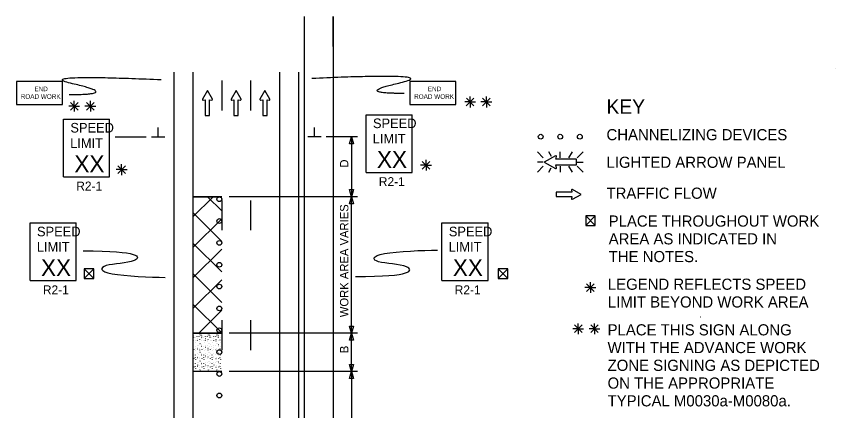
# Model space of a CAD drawing. Extents: x 16590 to 19508, y 5703 to 6974.
# Drawn here: x 16741 to 17424, y 6645 to 6974 of the extents above; entities that cross this region are included whole.
import ezdxf

# ---------------------------------------------------------------- set-up
doc = ezdxf.new("R2010")
doc.units = 0
for name, color, linetype in [('ALI_LEGAL_EX', 7, 'Continuous'), ('BORDER', 7, 'Continuous'), ('MT_SCRATCH_LEVEL_E', 7, 'Continuous'), ('PAVT_EDGE_EX', 7, 'Continuous'), ('TRAFFIC_SIGNS_PR', 7, 'Continuous'), ('TYPICAL_TEXT_DIMEN_EX', 7, 'Continuous'), ('TYPICAL_TEXT_DIMEN_PR', 7, 'Continuous')]:
    doc.layers.add(name, color=color, linetype=linetype)

msp = doc.modelspace()

# ---------------------------------------------------------------- linework, layer by layer
at = {"layer": 'ALI_LEGAL_EX'}
for p, q in [((16980.68, 6974.12), (16980.68, 6155.98)), ((17004.68, 6974.12), (17004.68, 6155.98)), ((16980.68, 6922.21), (16980.68, 6058.3)), ((17004.68, 6922.21), (17004.68, 6058.3))]:
    msp.add_line(p, q, dxfattribs=at)
for points in [[(17004.68, 6949.12), (17004.68, 6974.12)], [(16911.96, 6920.69), (16911.96, 6895.69)], [(16935.96, 6920.69), (16935.96, 6895.69)], [(16911.96, 6820.69), (16911.96, 6795.69)], [(16935.96, 6820.69), (16935.96, 6795.69)], [(16911.96, 6720.69), (16911.96, 6695.69)], [(16935.96, 6720.69), (16935.96, 6695.69)]]:
    msp.add_lwpolyline(points, dxfattribs=at)
at = {"layer": 'BORDER'}
msp.add_line((17423.55, 6930.8), (17423.55, 6930.8), dxfattribs=at)
at = {"layer": 'MT_SCRATCH_LEVEL_E'}
for p, q in [((16899.96, 6912.2), (16895.85, 6904.96)), ((16904.1, 6904.96), (16899.96, 6912.2)), ((16923.86, 6912.2), (16919.75, 6904.96)), ((16928.01, 6904.96), (16923.86, 6912.2)), ((16947.91, 6912.2), (16943.8, 6904.96)), ((16952.06, 6904.96), (16947.91, 6912.2)), ((16896.33, 6904.28), (16898.1, 6904.59)), ((16898.1, 6904.59), (16898.1, 6891.34)), ((16901.85, 6891.34), (16901.85, 6904.59)), ((16901.85, 6904.59), (16903.62, 6904.28)), ((16920.23, 6904.28), (16922.01, 6904.59)), ((16922.01, 6904.59), (16922.01, 6891.34)), ((16925.75, 6891.34), (16925.75, 6904.59)), ((16925.75, 6904.59), (16927.53, 6904.28)), ((16944.28, 6904.28), (16946.06, 6904.59)), ((16946.06, 6904.59), (16946.06, 6891.34)), ((16949.8, 6891.34), (16949.8, 6904.59)), ((16949.8, 6904.59), (16951.58, 6904.28)), ((16898.1, 6891.34), (16901.85, 6891.34)), ((16922.01, 6891.34), (16925.75, 6891.34)), ((16946.06, 6891.34), (16949.8, 6891.34)), ((17203.46, 6829.33), (17203.77, 6827.55)), ((17211.38, 6825.7), (17204.14, 6829.81)), ((17203.77, 6827.55), (17190.52, 6827.55)), ((17190.52, 6827.55), (17190.52, 6823.81)), ((17190.52, 6823.81), (17203.77, 6823.81)), ((17203.77, 6823.81), (17203.46, 6822.03)), ((17204.14, 6821.55), (17211.38, 6825.7))]:
    msp.add_line(p, q, dxfattribs=at)
for centre, start, end in [((16896.25, 6904.74), 150.42484, 279.96381), ((16903.69, 6904.74), 260.03619, 29.77312), ((16920.16, 6904.74), 150.42484, 279.96381), ((16927.6, 6904.74), 260.03619, 29.77312), ((16944.21, 6904.74), 150.42484, 279.96381), ((16951.65, 6904.74), 260.03619, 29.77312), ((17203.92, 6829.4), 60.42484, 189.96381), ((17203.92, 6821.96), 170.03619, 299.77312)]:
    msp.add_arc(centre, 0.463, start, end, dxfattribs=at)
at = {"layer": 'PAVT_EDGE_EX'}
for p, q in [((16871.96, 6927.73), (16871.96, 6263.8)), ((16887.96, 6927.73), (16887.96, 6263.8)), ((16959.96, 6927.73), (16959.96, 6263.8)), ((16975.96, 6927.73), (16975.96, 6263.8)), ((16887.96, 6823.76), (16911.96, 6823.76)), ((16887.96, 6806.86), (16904.85, 6823.76)), ((16912.05, 6823.76), (16888.05, 6823.76)), ((16911.96, 6811.94), (16900.14, 6823.76)), ((16911.96, 6786.49), (16887.96, 6810.49)), ((16887.96, 6781.4), (16911.96, 6805.4)), ((16911.96, 6761.03), (16887.96, 6785.03)), ((16887.96, 6755.95), (16911.96, 6779.95)), ((16911.96, 6735.58), (16887.96, 6759.58)), ((16887.96, 6730.49), (16911.96, 6754.49)), ((16911.96, 6710.12), (16887.96, 6734.12)), ((16892.95, 6710.03), (16912.05, 6729.12)), ((16911.96, 6710.03), (16887.96, 6710.03)), ((16912.05, 6710.03), (16888.05, 6710.03)), ((16888.05, 6710.03), (16912.05, 6710.03)), ((16888.35, 6706.21), (16888.3, 6706.13)), ((16888.44, 6707.48), (16888.38, 6707.6)), ((16889.89, 6706.35), (16889.83, 6706.27)), ((16890.46, 6709.68), (16890.4, 6709.79)), ((16891.5, 6707.18), (16891.45, 6707.3)), ((16891.68, 6705.29), (16891.62, 6705.22)), ((16892.95, 6707.03), (16892.9, 6706.95)), ((16893.82, 6708.41), (16893.77, 6708.33)), ((16894.56, 6708.44), (16894.51, 6708.36)), ((16895.24, 6706.21), (16895.19, 6706.13)), ((16895.32, 6707.48), (16895.27, 6707.6)), ((16896.77, 6706.35), (16896.72, 6706.27)), ((16897.34, 6709.68), (16897.29, 6709.79)), ((16898.39, 6707.18), (16898.34, 6707.3)), ((16898.56, 6705.29), (16898.51, 6705.22)), ((16899.84, 6707.03), (16899.79, 6706.95)), ((16900.71, 6708.41), (16900.66, 6708.33)), ((16901.45, 6708.44), (16901.4, 6708.36)), ((16902.13, 6706.21), (16902.08, 6706.13)), ((16902.21, 6707.48), (16902.16, 6707.6)), ((16903.66, 6706.35), (16903.61, 6706.27)), ((16904.23, 6709.68), (16904.18, 6709.79)), ((16905.28, 6707.18), (16905.23, 6707.3)), ((16905.45, 6705.29), (16905.4, 6705.22)), ((16906.73, 6707.03), (16906.68, 6706.95)), ((16907.6, 6708.41), (16907.55, 6708.33)), ((16908.33, 6708.44), (16908.28, 6708.36)), ((16909.02, 6706.21), (16908.97, 6706.13)), ((16909.1, 6707.48), (16909.05, 6707.6)), ((16910.55, 6706.35), (16910.5, 6706.27)), ((16911.12, 6709.68), (16911.07, 6709.79)), ((16912.05, 6710.03), (16912.05, 6710.03)), ((16888.35, 6698.93), (16888.3, 6698.85)), ((16888.44, 6700.19), (16888.38, 6700.31)), ((16888.56, 6703.57), (16888.54, 6703.45)), ((16889.84, 6704.14), (16889.78, 6704.07)), ((16889.89, 6699.07), (16889.83, 6698.99)), ((16890.46, 6702.39), (16890.4, 6702.51)), ((16891.5, 6699.9), (16891.45, 6700.01)), ((16891.63, 6703.89), (16891.58, 6704.01)), ((16891.68, 6698.01), (16891.62, 6697.93)), ((16892.95, 6699.74), (16892.9, 6699.67)), ((16893.41, 6703.22), (16893.36, 6703.15)), ((16893.6, 6704.42), (16893.55, 6704.54)), ((16893.82, 6701.12), (16893.77, 6701.05)), ((16894.56, 6701.15), (16894.51, 6701.08)), ((16895.24, 6698.93), (16895.19, 6698.85)), ((16895.32, 6700.19), (16895.27, 6700.31)), ((16895.44, 6703.57), (16895.43, 6703.45)), ((16896.72, 6704.14), (16896.67, 6704.07)), ((16896.77, 6699.07), (16896.72, 6698.99)), ((16897.34, 6702.39), (16897.29, 6702.51)), ((16898.39, 6699.9), (16898.34, 6700.01)), ((16898.52, 6703.89), (16898.47, 6704.01)), ((16898.56, 6698.01), (16898.51, 6697.93)), ((16899.84, 6699.74), (16899.79, 6699.67)), ((16900.3, 6703.22), (16900.25, 6703.15)), ((16900.49, 6704.42), (16900.44, 6704.54)), ((16900.71, 6701.12), (16900.66, 6701.05)), ((16901.45, 6701.15), (16901.4, 6701.08)), ((16902.13, 6698.93), (16902.08, 6698.85)), ((16902.21, 6700.19), (16902.16, 6700.31)), ((16902.33, 6703.57), (16902.32, 6703.45)), ((16903.61, 6704.14), (16903.56, 6704.07)), ((16903.66, 6699.07), (16903.61, 6698.99)), ((16904.23, 6702.39), (16904.18, 6702.51)), ((16905.28, 6699.9), (16905.23, 6700.01)), ((16905.41, 6703.89), (16905.36, 6704.01)), ((16905.45, 6698.01), (16905.4, 6697.93)), ((16906.73, 6699.74), (16906.68, 6699.67)), ((16907.19, 6703.22), (16907.14, 6703.15)), ((16907.38, 6704.42), (16907.33, 6704.54)), ((16907.6, 6701.12), (16907.55, 6701.05)), ((16908.33, 6701.15), (16908.28, 6701.08)), ((16909.02, 6698.93), (16908.97, 6698.85)), ((16909.1, 6700.19), (16909.05, 6700.31)), ((16909.22, 6703.57), (16909.21, 6703.45)), ((16910.5, 6704.14), (16910.45, 6704.07)), ((16910.55, 6699.07), (16910.5, 6698.99)), ((16911.12, 6702.39), (16911.07, 6702.51)), ((16888.35, 6691.64), (16888.3, 6691.56)), ((16888.44, 6692.91), (16888.38, 6693.03)), ((16888.56, 6696.28), (16888.54, 6696.16)), ((16889.84, 6696.86), (16889.78, 6696.78)), ((16889.89, 6691.78), (16889.83, 6691.7)), ((16890.46, 6695.11), (16890.4, 6695.22)), ((16891.5, 6692.61), (16891.45, 6692.73)), ((16891.63, 6696.61), (16891.58, 6696.72)), ((16892.95, 6692.46), (16892.9, 6692.38)), ((16893.41, 6695.94), (16893.36, 6695.86)), ((16893.6, 6697.14), (16893.55, 6697.25)), ((16893.82, 6693.84), (16893.77, 6693.76)), ((16894.56, 6693.87), (16894.51, 6693.79)), ((16895.24, 6691.64), (16895.19, 6691.56)), ((16895.32, 6692.91), (16895.27, 6693.03)), ((16895.44, 6696.28), (16895.43, 6696.16)), ((16896.72, 6696.86), (16896.67, 6696.78)), ((16896.77, 6691.78), (16896.72, 6691.7)), ((16897.34, 6695.11), (16897.29, 6695.22)), ((16898.39, 6692.61), (16898.34, 6692.73)), ((16898.52, 6696.61), (16898.47, 6696.72)), ((16899.84, 6692.46), (16899.79, 6692.38)), ((16900.3, 6695.94), (16900.25, 6695.86)), ((16900.49, 6697.14), (16900.44, 6697.25)), ((16900.71, 6693.84), (16900.66, 6693.76)), ((16901.45, 6693.87), (16901.4, 6693.79)), ((16902.13, 6691.64), (16902.08, 6691.56)), ((16902.21, 6692.91), (16902.16, 6693.03)), ((16902.33, 6696.28), (16902.32, 6696.16)), ((16903.61, 6696.86), (16903.56, 6696.78)), ((16903.66, 6691.78), (16903.61, 6691.7)), ((16904.23, 6695.11), (16904.18, 6695.22)), ((16905.28, 6692.61), (16905.23, 6692.73)), ((16905.41, 6696.61), (16905.36, 6696.72)), ((16906.73, 6692.46), (16906.68, 6692.38)), ((16907.19, 6695.94), (16907.14, 6695.86)), ((16907.38, 6697.14), (16907.33, 6697.25)), ((16907.6, 6693.84), (16907.55, 6693.76)), ((16908.33, 6693.87), (16908.28, 6693.79)), ((16909.02, 6691.64), (16908.97, 6691.56)), ((16909.1, 6692.91), (16909.05, 6693.03)), ((16909.22, 6696.28), (16909.21, 6696.16)), ((16910.5, 6696.86), (16910.45, 6696.78)), ((16910.55, 6691.78), (16910.5, 6691.7)), ((16911.12, 6695.11), (16911.07, 6695.22)), ((16888.35, 6684.36), (16888.3, 6684.28)), ((16888.44, 6685.62), (16888.38, 6685.74)), ((16888.56, 6689), (16888.54, 6688.88)), ((16889.84, 6689.57), (16889.78, 6689.49)), ((16889.89, 6684.5), (16889.83, 6684.42)), ((16890.46, 6687.82), (16890.4, 6687.94)), ((16891.5, 6685.33), (16891.45, 6685.44)), ((16891.63, 6689.32), (16891.58, 6689.44)), ((16891.68, 6690.72), (16891.62, 6690.65)), ((16892.95, 6685.18), (16892.9, 6685.1)), ((16893.41, 6688.65), (16893.36, 6688.58)), ((16893.6, 6689.85), (16893.55, 6689.97)), ((16893.82, 6686.55), (16893.77, 6686.48)), ((16894.56, 6686.58), (16894.51, 6686.51)), ((16895.24, 6684.36), (16895.19, 6684.28)), ((16895.32, 6685.62), (16895.27, 6685.74)), ((16895.44, 6689), (16895.43, 6688.88)), ((16896.72, 6689.57), (16896.67, 6689.49)), ((16896.77, 6684.5), (16896.72, 6684.42)), ((16897.34, 6687.82), (16897.29, 6687.94)), ((16898.39, 6685.33), (16898.34, 6685.44)), ((16898.52, 6689.32), (16898.47, 6689.44)), ((16898.56, 6690.72), (16898.51, 6690.65)), ((16899.84, 6685.18), (16899.79, 6685.1)), ((16900.3, 6688.65), (16900.25, 6688.58)), ((16900.49, 6689.85), (16900.44, 6689.97)), ((16900.71, 6686.55), (16900.66, 6686.48)), ((16901.45, 6686.58), (16901.4, 6686.51)), ((16902.13, 6684.36), (16902.08, 6684.28)), ((16902.21, 6685.62), (16902.16, 6685.74)), ((16902.33, 6689), (16902.32, 6688.88)), ((16903.61, 6689.57), (16903.56, 6689.49)), ((16903.66, 6684.5), (16903.61, 6684.42)), ((16904.23, 6687.82), (16904.18, 6687.94)), ((16905.28, 6685.33), (16905.23, 6685.44)), ((16905.41, 6689.32), (16905.36, 6689.44)), ((16905.45, 6690.72), (16905.4, 6690.65)), ((16906.73, 6685.18), (16906.68, 6685.1)), ((16907.19, 6688.65), (16907.14, 6688.58)), ((16907.38, 6689.85), (16907.33, 6689.97)), ((16907.6, 6686.55), (16907.55, 6686.48)), ((16908.33, 6686.58), (16908.28, 6686.51)), ((16909.02, 6684.36), (16908.97, 6684.28)), ((16909.1, 6685.62), (16909.05, 6685.74)), ((16909.22, 6689), (16909.21, 6688.88)), ((16910.5, 6689.57), (16910.45, 6689.49)), ((16910.55, 6684.5), (16910.5, 6684.42)), ((16911.12, 6687.82), (16911.07, 6687.94)), ((16911.96, 6677.97), (16887.96, 6677.97)), ((16912.05, 6677.97), (16888.05, 6677.97)), ((16888.44, 6678.34), (16888.38, 6678.45)), ((16888.56, 6681.71), (16888.54, 6681.6)), ((16889.84, 6682.29), (16889.78, 6682.21)), ((16890.46, 6680.53), (16890.4, 6680.65)), ((16891.5, 6678.04), (16891.45, 6678.16)), ((16891.63, 6682.04), (16891.58, 6682.15)), ((16891.68, 6683.44), (16891.62, 6683.36)), ((16893.41, 6681.37), (16893.36, 6681.29)), ((16893.6, 6682.57), (16893.55, 6682.69)), ((16893.82, 6679.27), (16893.77, 6679.19)), ((16894.56, 6679.3), (16894.51, 6679.22)), ((16895.32, 6678.34), (16895.27, 6678.45)), ((16895.44, 6681.71), (16895.43, 6681.6)), ((16896.72, 6682.29), (16896.67, 6682.21)), ((16897.34, 6680.53), (16897.29, 6680.65)), ((16898.39, 6678.04), (16898.34, 6678.16)), ((16898.52, 6682.04), (16898.47, 6682.15)), ((16898.56, 6683.44), (16898.51, 6683.36)), ((16900.3, 6681.37), (16900.25, 6681.29)), ((16900.49, 6682.57), (16900.44, 6682.69)), ((16900.71, 6679.27), (16900.66, 6679.19)), ((16901.45, 6679.3), (16901.4, 6679.22)), ((16902.21, 6678.34), (16902.16, 6678.45)), ((16902.33, 6681.71), (16902.32, 6681.6)), ((16903.61, 6682.29), (16903.56, 6682.21)), ((16904.23, 6680.53), (16904.18, 6680.65)), ((16905.28, 6678.04), (16905.23, 6678.16)), ((16905.41, 6682.04), (16905.36, 6682.15)), ((16905.45, 6683.44), (16905.4, 6683.36)), ((16907.19, 6681.37), (16907.14, 6681.29)), ((16907.38, 6682.57), (16907.33, 6682.69)), ((16907.6, 6679.27), (16907.55, 6679.19)), ((16908.33, 6679.3), (16908.28, 6679.22)), ((16909.1, 6678.34), (16909.05, 6678.45)), ((16909.22, 6681.71), (16909.21, 6681.6)), ((16910.5, 6682.29), (16910.45, 6682.21)), ((16911.12, 6680.53), (16911.07, 6680.65))]:
    msp.add_line(p, q, dxfattribs=at)
at = {"layer": 'TRAFFIC_SIGNS_PR'}
for p, q in [((17032.18, 6892.08), (17070.63, 6892.08)), ((17032.18, 6844.02), (17032.18, 6892.08)), ((17070.63, 6844.02), (17070.63, 6892.08)), ((16780, 6888.4), (16818.45, 6888.4)), ((16780, 6840.34), (16780, 6888.4)), ((16818.45, 6840.34), (16818.45, 6888.4)), ((17174.97, 6861.12), (17179.9, 6856.19)), ((17186.73, 6857.31), (17184.52, 6861.13)), ((17194.05, 6856.19), (17194.05, 6861.13)), ((17201.29, 6856.19), (17204.14, 6861.13)), ((17208.2, 6856.19), (17213.14, 6861.13)), ((17179.9, 6852.64), (17174.97, 6852.64)), ((17174.97, 6844.15), (17179.9, 6849.08)), ((17194.05, 6849.08), (17194.05, 6844.15)), ((17204.18, 6844.15), (17201.33, 6849.08)), ((17208.2, 6852.64), (17213.14, 6852.64)), ((17208.2, 6849.08), (17213.14, 6844.15)), ((17032.18, 6844.02), (17070.63, 6844.02)), ((17184.48, 6844.15), (17186.59, 6847.81)), ((16780, 6840.34), (16818.45, 6840.34)), ((16752.19, 6801.84), (16790.64, 6801.84)), ((16752.19, 6753.78), (16752.19, 6801.84)), ((16790.64, 6753.78), (16790.64, 6801.84)), ((17095.41, 6801.84), (17133.86, 6801.84)), ((17095.41, 6753.78), (17095.41, 6801.84)), ((17133.86, 6753.78), (17133.86, 6801.84)), ((16752.19, 6753.78), (16790.64, 6753.78)), ((17095.41, 6753.78), (17133.86, 6753.78))]:
    msp.add_line(p, q, dxfattribs=at)
for points in [[(16740.79, 6900.6), (16779.24, 6900.6), (16779.24, 6919.82), (16740.79, 6919.82)], [(17068.64, 6900.6), (17107.08, 6900.6), (17107.08, 6919.82), (17068.64, 6919.82)]]:
    msp.add_lwpolyline(points, close=True, dxfattribs=at)
for points in [[(17189.98, 6857.91), (17180.69, 6852.64), (17189.98, 6847.32)], [(17190.85, 6847.94), (17190.45, 6850.21), (17207.47, 6850.21), (17207.47, 6855.01), (17190.45, 6855.01), (17190.86, 6857.3)]]:
    msp.add_lwpolyline(points, dxfattribs=at)
for centre in [(17177.76, 6873.75), (17194.06, 6873.75), (17210.36, 6873.75), (16909.95, 6821.64), (16909.95, 6803.42), (16909.95, 6785.21), (16909.95, 6766.99), (16909.95, 6748.78), (16909.95, 6730.56), (16909.95, 6712.35), (16909.95, 6694.14), (16909.95, 6675.92), (16909.95, 6657.92)]:
    msp.add_circle(centre, 2, dxfattribs=at)
for centre, radius, start, end in [((17190.27, 6857.39), 0.598, 350.73078, 118.89165), ((17190.26, 6847.84), 0.597, 241.48329, 9.95933)]:
    msp.add_arc(centre, radius, start, end, dxfattribs=at)
for points in [[(17063.92, 6909.83), (17021.41, 6909.83), (17097.93, 6927.24), (16987.14, 6922.3)], [(16784.71, 6908.91), (16827.22, 6908.91), (16750.7, 6926.32), (16861.49, 6921.38)]]:
    msp.add_open_spline(points, degree=2, dxfattribs=at)
at = {"layer": 'TYPICAL_TEXT_DIMEN_PR'}
for p, q in [((16788.97, 6899.17), (16788.97, 6903.63)), ((16802.47, 6899.17), (16802.47, 6903.63)), ((17122.16, 6905.91), (17115.78, 6899.53)), ((17115.79, 6905.91), (17122.16, 6899.53)), ((17118.97, 6902.72), (17118.97, 6907.18)), ((17129.29, 6905.91), (17135.67, 6899.53)), ((17135.67, 6905.91), (17129.29, 6899.53)), ((17132.48, 6902.72), (17132.48, 6907.18)), ((16788.97, 6899.17), (16784.43, 6899.17)), ((16785.78, 6902.36), (16792.15, 6895.99)), ((16792.15, 6902.36), (16785.78, 6895.99)), ((16788.97, 6899.17), (16792.15, 6899.17)), ((16788.97, 6899.17), (16793.44, 6899.17)), ((16788.97, 6899.17), (16788.97, 6894.67)), ((16802.47, 6899.17), (16797.94, 6899.17)), ((16799.28, 6902.36), (16805.66, 6895.99)), ((16805.66, 6902.36), (16799.28, 6895.99)), ((16802.47, 6899.17), (16805.66, 6899.17)), ((16802.47, 6899.17), (16806.95, 6899.17)), ((16802.47, 6899.17), (16802.47, 6894.67)), ((17118.97, 6902.72), (17114.44, 6902.72)), ((17118.97, 6902.72), (17122.16, 6902.72)), ((17118.97, 6902.72), (17123.45, 6902.72)), ((17118.97, 6902.72), (17118.97, 6898.22)), ((17132.48, 6902.72), (17127.95, 6902.72)), ((17132.48, 6902.72), (17135.67, 6902.72)), ((17132.48, 6902.72), (17136.96, 6902.72)), ((17132.48, 6902.72), (17132.48, 6898.22)), ((16858.92, 6873.76), (16858.92, 6881.54)), ((16989.17, 6873.76), (16989.17, 6881.54)), ((16823.05, 6873.76), (16849.05, 6873.76)), ((16853.3, 6873.76), (16864.55, 6873.76)), ((16994.8, 6873.76), (16983.55, 6873.76)), ((17025.05, 6873.76), (16999.05, 6873.76)), ((17018.47, 6867.9), (17020.05, 6873.76)), ((17020.05, 6873.76), (17020.05, 6823.76)), ((17020.05, 6873.76), (17021.62, 6867.9)), ((17020.05, 6867.9), (17018.47, 6867.9)), ((17021.62, 6867.9), (17020.05, 6867.9)), ((16831.7, 6849.47), (16825.32, 6843.1)), ((16825.33, 6849.47), (16831.7, 6843.1)), ((16828.51, 6846.29), (16828.51, 6850.74)), ((17082.22, 6849.97), (17077.69, 6849.97)), ((17079.04, 6853.15), (17085.41, 6846.78)), ((17085.41, 6853.15), (17079.04, 6846.78)), ((17082.22, 6849.97), (17082.22, 6854.42)), ((17082.22, 6849.97), (17085.41, 6849.97)), ((17082.22, 6849.97), (17086.7, 6849.97)), ((17082.22, 6849.97), (17082.22, 6845.47)), ((16828.51, 6846.29), (16823.98, 6846.29)), ((16828.51, 6846.29), (16831.7, 6846.29)), ((16828.51, 6846.29), (16832.99, 6846.29)), ((16828.51, 6846.29), (16828.51, 6841.79)), ((17020.05, 6823.76), (17018.47, 6829.62)), ((17018.47, 6829.62), (17020.05, 6829.62)), ((17020.05, 6829.62), (17021.62, 6829.62)), ((17021.62, 6829.62), (17020.05, 6823.76)), ((17025.05, 6823.76), (16918.04, 6823.76)), ((17018.47, 6817.9), (17020.05, 6823.76)), ((17020.05, 6710.03), (17020.05, 6823.76)), ((17020.05, 6823.76), (17021.62, 6817.9)), ((17020.05, 6817.9), (17018.47, 6817.9)), ((17021.62, 6817.9), (17020.05, 6817.9)), ((17215.24, 6807.77), (17223.24, 6799.77)), ((17215.24, 6799.77), (17223.24, 6807.77)), ((16797.39, 6763.56), (16805.39, 6755.56)), ((16797.39, 6755.56), (16805.39, 6763.56)), ((17142.31, 6763.56), (17150.31, 6755.56)), ((17142.31, 6755.56), (17150.31, 6763.56)), ((17219.2, 6748), (17214.67, 6748)), ((17216.01, 6751.19), (17222.39, 6744.81)), ((17222.39, 6751.19), (17216.01, 6744.81)), ((17219.2, 6748), (17219.2, 6752.46)), ((17219.2, 6748), (17222.39, 6748)), ((17219.2, 6748), (17223.67, 6748)), ((17219.2, 6748), (17219.2, 6743.5)), ((17020.05, 6710.03), (17018.47, 6715.9)), ((17018.47, 6715.9), (17020.05, 6715.9)), ((17020.05, 6715.9), (17021.62, 6715.9)), ((17021.62, 6715.9), (17020.05, 6710.03)), ((17209.1, 6713.6), (17204.56, 6713.6)), ((17205.91, 6716.79), (17212.28, 6710.41)), ((17212.28, 6716.79), (17205.91, 6710.41)), ((17209.1, 6713.6), (17209.1, 6718.06)), ((17209.1, 6713.6), (17212.28, 6713.6)), ((17209.1, 6713.6), (17213.57, 6713.6)), ((17209.1, 6713.6), (17209.1, 6709.1)), ((17222.6, 6713.6), (17218.07, 6713.6)), ((17225.79, 6716.79), (17219.41, 6710.41)), ((17219.42, 6716.79), (17225.79, 6710.41)), ((17222.6, 6713.6), (17222.6, 6718.06)), ((17222.6, 6713.6), (17225.79, 6713.6)), ((17222.6, 6713.6), (17227.08, 6713.6)), ((17222.6, 6713.6), (17222.6, 6709.1)), ((17025.05, 6710.03), (16918.04, 6710.03)), ((17018.47, 6704.17), (17020.05, 6710.03)), ((17020.05, 6677.97), (17020.05, 6710.03)), ((17020.05, 6710.03), (17021.62, 6704.17)), ((17020.05, 6704.17), (17018.47, 6704.17)), ((17021.62, 6704.17), (17020.05, 6704.17)), ((17025.05, 6677.97), (16918.04, 6677.97)), ((17020.05, 6677.97), (17018.47, 6683.84)), ((17018.47, 6683.84), (17020.05, 6683.84)), ((17018.47, 6672.11), (17020.05, 6677.97)), ((17020.05, 6677.97), (17019.96, 6585.92)), ((17020.05, 6683.84), (17021.62, 6683.84)), ((17021.62, 6683.84), (17020.05, 6677.97)), ((17020.05, 6677.97), (17021.62, 6672.11)), ((17020.05, 6672.11), (17018.47, 6672.11)), ((17021.62, 6672.11), (17020.05, 6672.11))]:
    msp.add_line(p, q, dxfattribs=at)
for points in [[(17215.24, 6807.77), (17215.24, 6799.77), (17223.24, 6799.77), (17223.24, 6807.77)], [(16797.39, 6763.56), (16797.39, 6755.56), (16805.39, 6755.56), (16805.39, 6763.56)], [(17142.31, 6763.56), (17142.31, 6755.56), (17150.31, 6755.56), (17150.31, 6763.56)]]:
    msp.add_lwpolyline(points, close=True, dxfattribs=at)
for points, degree in [([(16796.35, 6778.66), (16844.82, 6778.66), (16844.82, 6767.9), (16809.9, 6767.9), (16809.9, 6758.24), (16852.76, 6756.72), (16864.67, 6756.46)], 3), ([(17023.35, 6757.09), (17071.82, 6757.09), (17071.82, 6767.84), (17036.9, 6767.84), (17036.9, 6777.51), (17079.76, 6779.03), (17091.67, 6779.28)], 3), ([(17116.1, 6779.57), (17116.11, 6779.57), (17116.12, 6779.57), (17116.12, 6779.57)], 2), ([(17310.78, 6723.42), (17310.81, 6723.42), (17310.81, 6723.42), (17310.81, 6723.42)], 2)]:
    msp.add_open_spline(points, degree=degree, dxfattribs=at)

# ---------------------------------------------------------------- texts
at = {"layer": 'TRAFFIC_SIGNS_PR'}
for s, height, p in [('END', 3.836, (16755.81, 6911.74)), ('END', 3.836, (17083.65, 6911.74)), ('ROAD WORK', 3.836, (16744.4, 6905.35)), ('ROAD WORK', 3.836, (17072.25, 6905.35)), ('SPEED', 8.01, (16785.78, 6877.25)), ('SPEED', 8.01, (17037.95, 6880.93)), ('LIMIT', 8.01, (17037.79, 6868.11)), ('LIMIT', 8.01, (16785.61, 6864.43)), ('XX', 14.048, (17041.3, 6847.78)), ('XX', 14.048, (16789.13, 6844.1)), ('R2-1', 7.449, (16790.69, 6828.89)), ('R2-1', 7.449, (17042.87, 6832.56)), ('SPEED', 8.01, (16757.96, 6790.69)), ('SPEED', 8.01, (17101.18, 6790.69)), ('LIMIT', 8.01, (16757.8, 6777.87)), ('LIMIT', 8.01, (17101.02, 6777.87)), ('XX', 14.048, (16761.31, 6757.54)), ('XX', 14.048, (17104.53, 6757.54)), ('R2-1', 7.449, (16762.88, 6742.33)), ('R2-1', 7.449, (17106.1, 6742.33))]:
    msp.add_text(s, height=height, dxfattribs=at).set_placement(p)
at = {"layer": 'TYPICAL_TEXT_DIMEN_EX'}
for s, height, p in [('KEY', 12, (17232.6, 6892.86)), ('CHANNELIZING DEVICES', 9.3, (17232.6, 6870.81)), ('LIGHTED ARROW PANEL', 9.3, (17232.6, 6847.81)), ('TRAFFIC FLOW', 9.3, (17232.6, 6822.01)), ('PLACE THROUGHOUT WORK', 9.3, (17234.42, 6798.76)), ('AREA AS INDICATED IN', 9.3, (17234.42, 6783.96)), ('THE NOTES.', 9.3, (17234.42, 6769.16)), ('LEGEND REFLECTS SPEED', 9.3, (17233.75, 6746.1)), ('LIMIT BEYOND WORK AREA', 9.3, (17233.75, 6731.3)), ('PLACE THIS SIGN ALONG', 9.3, (17233.51, 6708.06)), ('WITH THE ADVANCE WORK', 9.3, (17233.51, 6693.26)), ('ZONE SIGNING AS DEPICTED', 9.3, (17233.51, 6678.46)), ('ON THE APPROPRIATE', 9.3, (17233.51, 6663.66)), ('TYPICAL M0030a-M0080a.', 9.3, (17233.51, 6648.86))]:
    msp.add_text(s, height=height, dxfattribs=at).set_placement(p)
at = {"layer": 'TYPICAL_TEXT_DIMEN_PR'}
for s, p in [('D', (17017.49, 6847.98)), ('WORK AREA VARIES', (17017.49, 6723.25)), ('B', (17017.49, 6693.24))]:
    msp.add_text(s, height=7, rotation=90, dxfattribs=at).set_placement(p)

doc.saveas('drawing.dxf')
